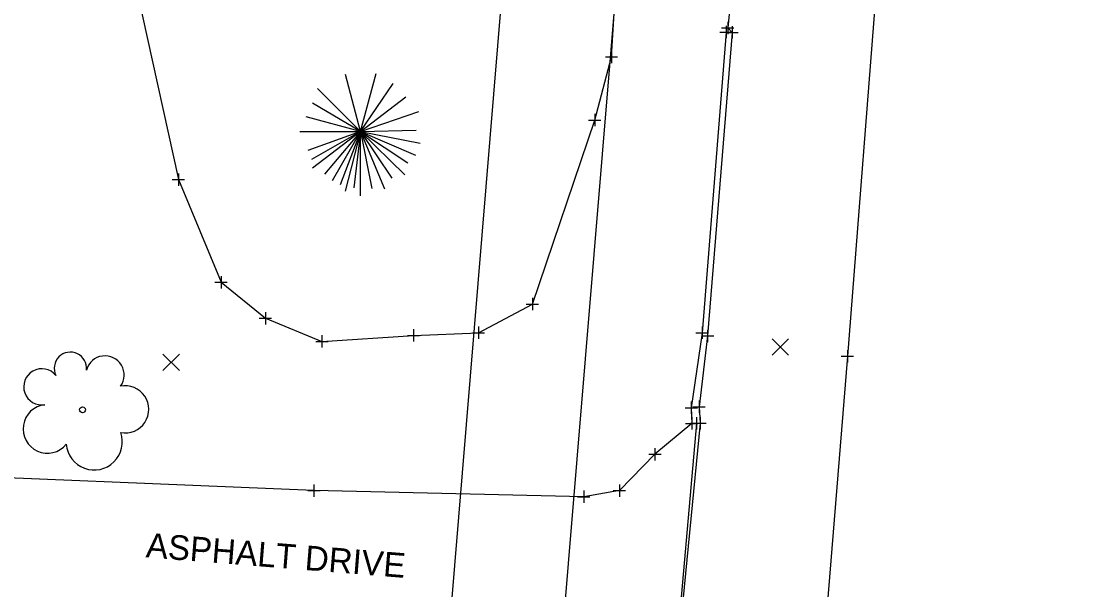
# Model space of a CAD drawing. Extents: x 1380550 to 1381945, y 468927 to 470496.
# Drawn here: x 1381505.7 to 1381592.3, y 469638.6 to 469684.8 of the extents above; entities that cross this region are included whole.
import ezdxf

# ---------------------------------------------------------------- set-up
doc = ezdxf.new("R2010")
doc.units = 0
for name, color, linetype in [('PV_X_COP', 7, 'Continuous'), ('PV_X_Curb', 7, 'Continuous'), ('PV_X_Driveway', 7, 'Continuous'), ('PV_X_EOP', 7, 'Continuous'), ('RD_X_Text', 7, 'Continuous'), ('RW_X_Esmt_General', 7, 'Continuous'), ('SV_X_Random_Point', 7, 'Continuous'), ('SV_X_Shot_Marker', 7, 'Continuous'), ('UT_X_Electric', 7, 'Continuous'), ('UT_X_Telecom', 7, 'Continuous'), ('VG_X_Cells', 7, 'Continuous'), ('VG_X_Flower_Bed', 7, 'Continuous')]:
    doc.layers.add(name, color=color, linetype=linetype)

msp = doc.modelspace()

# ---------------------------------------------------------------- linework, layer by layer
at = {"layer": 'PV_X_COP'}
msp.add_lwpolyline([(1381585.986, 469815.579), (1381581.288, 469760.779), (1381580.3, 469747.86), (1381578.724, 469729.445), (1381576.782, 469708.953), (1381575.288, 469689.792), (1381572.756, 469657.561), (1381569.364, 469615.703), (1381565.36, 469567.235), (1381561.161, 469537.516), (1381558.939, 469486.814), (1381555.385, 469442.034), (1381550.974, 469391.016), (1381547.282, 469345.901), (1381541.953, 469289.547), (1381537.187, 469231.269), (1381533.052, 469168.087), (1381530.317, 469133.741), (1381523.968, 469065.081), (1381520.119, 469021.37), (1381518.183, 469001.306)], dxfattribs=at)
at = {"layer": 'PV_X_Curb'}
msp.add_lwpolyline([(1381562.909, 469683.886), (1381560.965, 469659.472), (1381560.08, 469653.376), (1381560.126, 469652.106)], dxfattribs=at)
at = {"layer": 'PV_X_Driveway'}
for points in [[(1381560.126, 469652.106), (1381557.126, 469649.606), (1381554.247, 469646.657), (1381551.359, 469646.158), (1381529.451, 469646.655), (1381494.053, 469648.135)], [(1381560.126, 469652.106), (1381560.507, 469652.116), (1381558.756, 469632.153)]]:
    msp.add_lwpolyline(points, dxfattribs=at)
at = {"layer": 'PV_X_EOP'}
msp.add_lwpolyline([(1381563.724, 469691.131), (1381563.046, 469684.218), (1381563.399, 469683.858), (1381561.402, 469659.212), (1381560.721, 469653.459), (1381560.796, 469652.125), (1381558.846, 469632.165), (1381558.208, 469631.211), (1381558.139, 469626.985), (1381558.609, 469626.56), (1381558.033, 469616.672), (1381557.48, 469616.691), (1381556.808, 469608.321), (1381557.185, 469608.373), (1381556.031, 469592.311), (1381555.444, 469591.97), (1381554.196, 469589.154), (1381555.272, 469588.129), (1381553.938, 469570.463), (1381553.845, 469569.157), (1381551.394, 469538.56)], dxfattribs=at)
at = {"layer": 'RW_X_Esmt_General'}
msp.add_lwpolyline([(1381490.401, 469029.464), (1381590.199, 470237.184), (1380558.689, 470277.035)], dxfattribs=at)
at = {"layer": 'SV_X_Random_Point'}
for p, q in [((1381566.647, 469657.64), (1381567.981, 469658.976)), ((1381566.647, 469658.976), (1381567.981, 469657.64)), ((1381517.192, 469656.397), (1381518.526, 469657.732)), ((1381517.192, 469657.732), (1381518.526, 469656.397))]:
    msp.add_line(p, q, dxfattribs=at)
at = {"layer": 'SV_X_Shot_Marker'}
for p, q in [((1381563.046, 469684.718), (1381563.046, 469683.718)), ((1381562.409, 469683.886), (1381563.409, 469683.886)), ((1381562.546, 469684.218), (1381563.546, 469684.218)), ((1381562.899, 469683.858), (1381563.899, 469683.858)), ((1381562.909, 469684.386), (1381562.909, 469683.386)), ((1381562.909, 469683.886), (1381562.909, 469683.886)), ((1381563.046, 469684.218), (1381563.046, 469684.218)), ((1381563.399, 469684.358), (1381563.399, 469683.358)), ((1381563.399, 469683.858), (1381563.399, 469683.858)), ((1381553.607, 469682.365), (1381553.607, 469681.365)), ((1381553.107, 469681.865), (1381554.107, 469681.865)), ((1381553.607, 469681.865), (1381553.607, 469681.865)), ((1381551.744, 469676.734), (1381552.744, 469676.734)), ((1381552.244, 469677.234), (1381552.244, 469676.234)), ((1381552.244, 469676.734), (1381552.244, 469676.734)), ((1381518.445, 469672.412), (1381518.445, 469671.412)), ((1381517.945, 469671.912), (1381518.945, 469671.912)), ((1381518.445, 469671.912), (1381518.445, 469671.912)), ((1381521.909, 469664.075), (1381521.909, 469663.075)), ((1381521.409, 469663.575), (1381522.409, 469663.575)), ((1381521.909, 469663.575), (1381521.909, 469663.575)), ((1381547.18, 469662.294), (1381547.18, 469661.294)), ((1381525.513, 469661.151), (1381525.513, 469660.151)), ((1381546.68, 469661.794), (1381547.68, 469661.794)), ((1381547.18, 469661.794), (1381547.18, 469661.794)), ((1381525.013, 469660.651), (1381526.013, 469660.651)), ((1381525.513, 469660.651), (1381525.513, 469660.651)), ((1381537.531, 469659.749), (1381537.531, 469658.749)), ((1381542.309, 469659.471), (1381543.309, 469659.471)), ((1381542.809, 469659.971), (1381542.809, 469658.971)), ((1381542.809, 469659.471), (1381542.809, 469659.471)), ((1381560.465, 469659.472), (1381561.465, 469659.472)), ((1381560.965, 469659.972), (1381560.965, 469658.972)), ((1381560.965, 469659.472), (1381560.965, 469659.472)), ((1381561.402, 469659.712), (1381561.402, 469658.712)), ((1381529.6, 469658.767), (1381530.6, 469658.767)), ((1381530.1, 469659.267), (1381530.1, 469658.267)), ((1381530.1, 469658.767), (1381530.1, 469658.767)), ((1381537.031, 469659.249), (1381538.031, 469659.249)), ((1381537.531, 469659.249), (1381537.531, 469659.249)), ((1381560.902, 469659.212), (1381561.902, 469659.212)), ((1381561.402, 469659.212), (1381561.402, 469659.212)), ((1381572.756, 469658.061), (1381572.756, 469657.061)), ((1381572.256, 469657.561), (1381573.256, 469657.561)), ((1381572.756, 469657.561), (1381572.756, 469657.561)), ((1381559.58, 469653.376), (1381560.58, 469653.376)), ((1381560.08, 469653.876), (1381560.08, 469652.876)), ((1381560.08, 469653.376), (1381560.08, 469653.376)), ((1381560.221, 469653.459), (1381561.221, 469653.459)), ((1381560.721, 469653.959), (1381560.721, 469652.959)), ((1381560.721, 469653.459), (1381560.721, 469653.459)), ((1381560.126, 469652.606), (1381560.126, 469651.606)), ((1381560.126, 469652.606), (1381560.126, 469651.606)), ((1381560.126, 469652.606), (1381560.126, 469651.606)), ((1381560.507, 469652.616), (1381560.507, 469651.616)), ((1381560.796, 469652.625), (1381560.796, 469651.625)), ((1381559.626, 469652.106), (1381560.626, 469652.106)), ((1381559.626, 469652.106), (1381560.626, 469652.106)), ((1381559.626, 469652.106), (1381560.626, 469652.106)), ((1381560.007, 469652.116), (1381561.007, 469652.116)), ((1381560.126, 469652.106), (1381560.126, 469652.106)), ((1381560.126, 469652.106), (1381560.126, 469652.106)), ((1381560.126, 469652.106), (1381560.126, 469652.106)), ((1381560.296, 469652.125), (1381561.296, 469652.125)), ((1381560.507, 469652.116), (1381560.507, 469652.116)), ((1381560.796, 469652.125), (1381560.796, 469652.125)), ((1381557.126, 469650.106), (1381557.126, 469649.106)), ((1381557.126, 469650.106), (1381557.126, 469649.106)), ((1381556.626, 469649.606), (1381557.626, 469649.606)), ((1381556.626, 469649.606), (1381557.626, 469649.606)), ((1381557.126, 469649.606), (1381557.126, 469649.606)), ((1381557.126, 469649.606), (1381557.126, 469649.606)), ((1381528.951, 469646.655), (1381529.951, 469646.655)), ((1381529.451, 469647.155), (1381529.451, 469646.155)), ((1381529.451, 469646.655), (1381529.451, 469646.655)), ((1381551.359, 469646.658), (1381551.359, 469645.658)), ((1381551.359, 469646.658), (1381551.359, 469645.658)), ((1381553.747, 469646.657), (1381554.747, 469646.657)), ((1381554.247, 469647.157), (1381554.247, 469646.157)), ((1381554.247, 469646.657), (1381554.247, 469646.657)), ((1381550.859, 469646.158), (1381551.859, 469646.158)), ((1381550.859, 469646.158), (1381551.859, 469646.158)), ((1381551.359, 469646.158), (1381551.359, 469646.158)), ((1381551.359, 469646.158), (1381551.359, 469646.158))]:
    msp.add_line(p, q, dxfattribs=at)
at = {"layer": 'UT_X_Electric'}
msp.add_lwpolyline([(1381665.562, 470247.404), (1381595.795, 470220.833), (1381581.264, 470018.199), (1381571.968, 469887.64), (1381559.775, 469757.408), (1381543.86, 469565.781), (1381529.165, 469390.12), (1381515.279, 469203.101), (1381540.8, 469054.263)], dxfattribs=at)
at = {"layer": 'UT_X_Telecom'}
msp.add_lwpolyline([(1381665.562, 470247.404), (1381595.346, 470217.51), (1381581.264, 470018.199), (1381571.968, 469887.64), (1381559.775, 469757.408), (1381543.86, 469565.781), (1381529.165, 469390.12), (1381515.279, 469203.101), (1381540.8, 469054.263)], dxfattribs=at)
at = {"layer": 'VG_X_Cells'}
for p, q in [((1381533.239, 469675.824), (1381532.004, 469680.437)), ((1381533.239, 469675.824), (1381534.496, 469680.522)), ((1381533.239, 469675.824), (1381529.749, 469679.311)), ((1381533.239, 469675.824), (1381535.894, 469679.709)), ((1381533.239, 469675.824), (1381536.896, 469678.629)), ((1381533.239, 469675.824), (1381529.332, 469678.121)), ((1381533.239, 469675.824), (1381528.826, 469677.007)), ((1381533.239, 469675.824), (1381537.976, 469677.431)), ((1381533.239, 469675.824), (1381537.749, 469675.916)), ((1381528.304, 469675.824), (1381533.239, 469675.824)), ((1381533.239, 469675.824), (1381528.949, 469674.262)), ((1381533.239, 469675.824), (1381529.256, 469673.542)), ((1381533.239, 469675.824), (1381529.332, 469672.829)), ((1381533.239, 469675.824), (1381530.294, 469672.357)), ((1381533.239, 469675.824), (1381530.921, 469671.809)), ((1381533.239, 469675.824), (1381531.574, 469671.484)), ((1381533.239, 469675.824), (1381531.976, 469670.967)), ((1381533.239, 469675.824), (1381532.697, 469671.232)), ((1381533.239, 469670.584), (1381533.239, 469675.824)), ((1381533.239, 469675.824), (1381534.161, 469671.187)), ((1381533.239, 469675.824), (1381535.172, 469671.156)), ((1381533.239, 469675.824), (1381535.776, 469672.031)), ((1381533.239, 469675.824), (1381536.827, 469672.302)), ((1381533.239, 469675.824), (1381537.061, 469673.269)), ((1381533.239, 469675.824), (1381537.704, 469673.882)), ((1381533.239, 469675.824), (1381538.067, 469674.866))]:
    msp.add_line(p, q, dxfattribs=at)
msp.add_circle((1381510.664, 469653.213), 0.24, dxfattribs=at)
for centre, radius, start, end in [((1381509.68, 469656.58), 1.317, 354.0047, 205.97412), ((1381512.49, 469656.042), 1.553, 323.82996, 165.0376), ((1381507.355, 469655.077), 1.471, 39.06254, 279.54124), ((1381514.124, 469653.249), 1.915, 259.14531, 101.45961), ((1381507.811, 469651.664), 1.974, 96.17219, 320.57371), ((1381511.61, 469650.607), 2.284, 184.94757, 19.45715)]:
    msp.add_arc(centre, radius, start, end, dxfattribs=at)
at = {"layer": 'VG_X_Flower_Bed'}
msp.add_lwpolyline([(1381553.607, 469681.865), (1381554.59, 469697.849), (1381554.018, 469701.129), (1381552.897, 469703.257), (1381550.416, 469704.97), (1381547.102, 469705.704), (1381540.463, 469707.051), (1381528.048, 469707.712), (1381525.41, 469706.805), (1381521.514, 469704.499), (1381517.196, 469699.242), (1381515.417, 469695.128), (1381515.514, 469685.296), (1381518.445, 469671.912), (1381521.909, 469663.575), (1381525.513, 469660.651), (1381530.1, 469658.767), (1381537.531, 469659.249), (1381542.809, 469659.471), (1381547.18, 469661.794), (1381552.244, 469676.734)], close=True, dxfattribs=at)

# ---------------------------------------------------------------- texts
at = {"layer": 'RD_X_Text'}
msp.add_text('ASPHALT DRIVE', height=2, rotation=355.44278, dxfattribs=at).set_placement((1381515.762, 469641.24))

doc.saveas('drawing.dxf')
